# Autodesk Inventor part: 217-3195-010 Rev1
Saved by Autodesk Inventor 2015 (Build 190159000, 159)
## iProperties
Created: 2014-11
Part Number: 217-3195-010 Rev1
Material: Generic
Document SubType Name: Modeling
Designer: User
Density: 1 g/cm^3
Appearance: Default
Author: User
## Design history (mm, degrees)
node "217-3195-010 Rev1.ipt1"
node "Fillet1"
node "Base1"
